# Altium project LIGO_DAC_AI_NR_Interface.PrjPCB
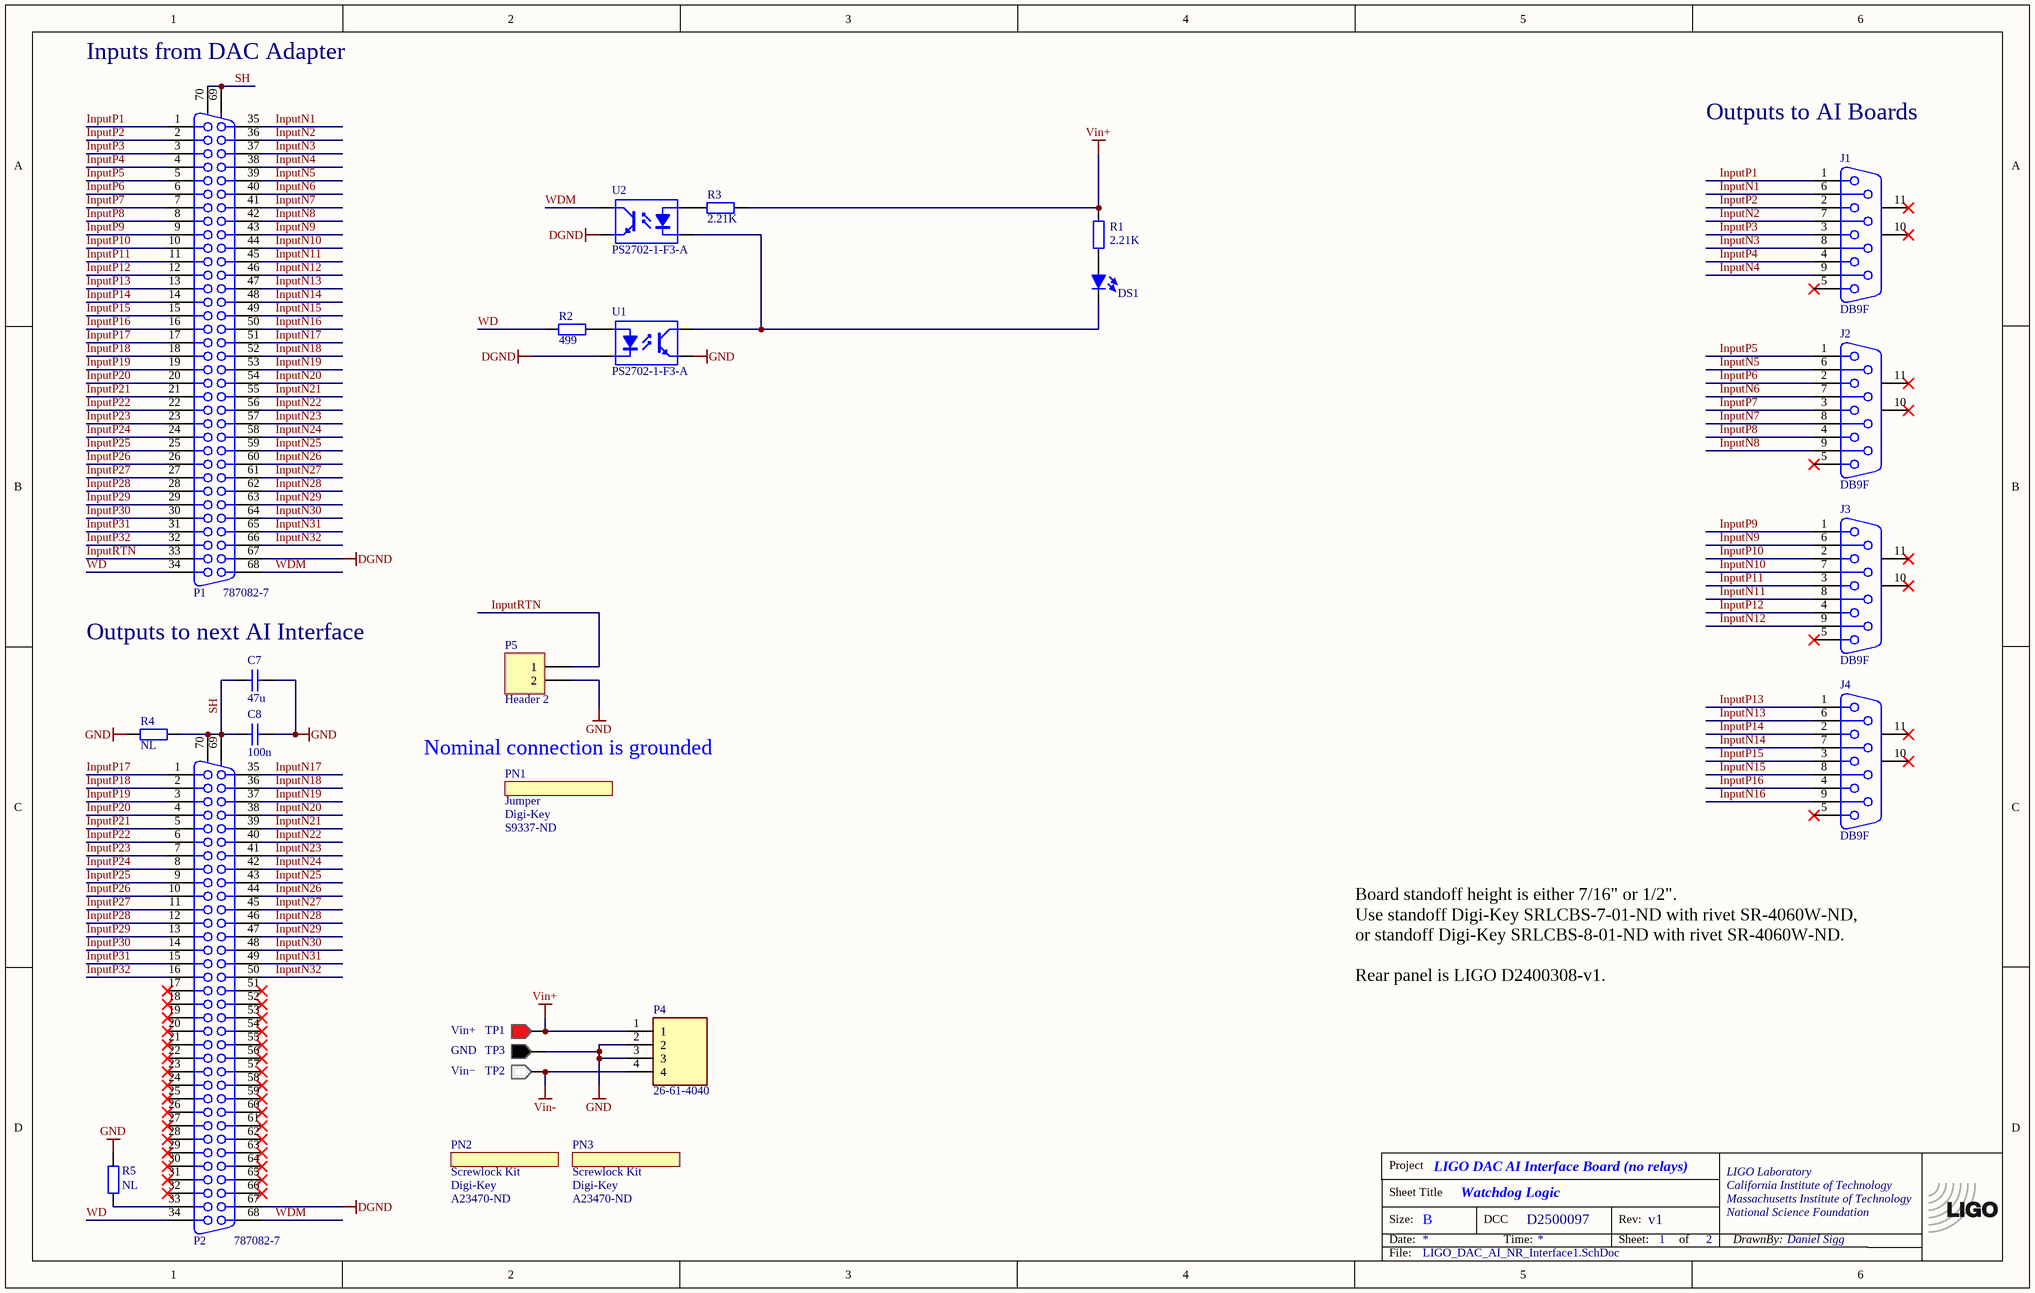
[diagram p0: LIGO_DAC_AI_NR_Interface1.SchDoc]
Rev: v1; Project: LIGO DAC AI Interface Board (no relays); Eng: Daniel Sigg; DCC: D2500097
1 sheet, 25 parts. Net scope: global (net labels, ports and power ports of the same name join across sheets).
Board file: LIGO_DAC_AI_NR_Interface.PcbDoc

## Sheet LIGO_DAC_AI_NR_Interface1.SchDoc: Watchdog Logic
size B; Engineer: Daniel Sigg; DocumentNumber: D2400023; Revision: v1; SheetNumber: 1; SheetTotal: 2; PageSetup: Record=PageOptions¦CenterHorizontal=True¦CenterVertical=True¦PrintScale=1.12¦XCorrection=1.00¦YCorrection=1.00¦PrintKind=0¦BorderSize=5000000¦LeftOffset=0¦BottomOffset=0¦Orientation=2¦PaperLength=1000¦PaperWidth=1000¦Scale=100¦PaperSource=15¦PrintQuality=600¦MediaType=1¦DitherType=10¦PaperKind=Tabloid¦PrintScaleMode=1; SHEETSIZE: B

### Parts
*?  TitleBlock  (value not drawn)  (graphical)
C7  47u  [CC5650-2220]
C8  100n  [CC2013-0805]
DS1  LED  [LED-1]  (value not drawn)
J1  DB9F  [DB9F-ST]
J2  DB9F  [DB9F-ST]
J3  DB9F  [DB9F-ST]
J4  DB9F  [DB9F-ST]
P1  787082-7  [787082-7]
P2  787082-7  [787082-7]
P4  26-61-4040  [HDRV4W155P0X396_1X4_1570X1001X1536P]
P5  Header 2  [TSW-102-XX-YY-S]
PN1  Jumper  Part Number: S9337-ND  Distributor: Digi-Key  (mechanical)
PN2  Screwlock Kit  Part Number: A23470-ND  Distributor: Digi-Key  (mechanical)
PN3  Screwlock Kit  Part Number: A23470-ND  Distributor: Digi-Key  (mechanical)
R1  2.21K  [CR2012-0805]
R2  499  [CR2012-0805]
R3  2.21K  [CR2012-0805]
R4  NL  [CR2012-0805]
R5  NL  [CR2012-0805]
TP1  Vin+  [TP1-RED]
TP2  Vin−  [TP1-WHT]
TP3  GND  [TP1-BLK]
U1  PS2702-1-F3-A  [PS2701A-1]
U2  PS2702-1-F3-A  [PS2701A-1]

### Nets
DGND: P1.67 P2.67 U1.2(K) U2.3(E)
GND: C7.1 C8.1 P4.2 P4.3 P5.2 R4.2 R5.2 TP3.1 U1.3(E)
Vin+: P4.1 R1.2 R3.2 TP1.1
Vin-: P4.4 TP2.1
InputN1: J1.6 P1.35
InputN2: J1.7 P1.36
InputN3: J1.8 P1.37
InputN4: J1.9 P1.38
InputN5: J2.6 P1.39
InputN6: J2.7 P1.40
InputN7: J2.8 P1.41
InputN8: J2.9 P1.42
InputN9: J3.6 P1.43
InputN10: J3.7 P1.44
InputN11: J3.8 P1.45
InputN12: J3.9 P1.46
InputN13: J4.6 P1.47
InputN14: J4.7 P1.48
InputN15: J4.8 P1.49
InputN16: J4.9 P1.50
InputN17: P1.51 P2.35
InputN18: P1.52 P2.36
InputN19: P1.53 P2.37
InputN20: P1.54 P2.38
InputN21: P1.55 P2.39
InputN22: P1.56 P2.40
InputN23: P1.57 P2.41
InputN24: P1.58 P2.42
InputN25: P1.59 P2.43
InputN26: P1.60 P2.44
InputN27: P1.61 P2.45
InputN28: P1.62 P2.46
InputN29: P1.63 P2.47
InputN30: P1.64 P2.48
InputN31: P1.65 P2.49
InputN32: P1.66 P2.50
InputP1: J1.1 P1.1
InputP2: J1.2 P1.2
InputP3: J1.3 P1.3
InputP4: J1.4 P1.4
InputP5: J2.1 P1.5
InputP6: J2.2 P1.6
InputP7: J2.3 P1.7
InputP8: J2.4 P1.8
InputP9: J3.1 P1.9
InputP10: J3.2 P1.10
InputP11: J3.3 P1.11
InputP12: J3.4 P1.12
InputP13: J4.1 P1.13
InputP14: J4.2 P1.14
InputP15: J4.3 P1.15
InputP16: J4.4 P1.16
InputP17: P1.17 P2.1
InputP18: P1.18 P2.2
InputP19: P1.19 P2.3
InputP20: P1.20 P2.4
InputP21: P1.21 P2.5
InputP22: P1.22 P2.6
InputP23: P1.23 P2.7
InputP24: P1.24 P2.8
InputP25: P1.25 P2.9
InputP26: P1.26 P2.10
InputP27: P1.27 P2.11
InputP28: P1.28 P2.12
InputP29: P1.29 P2.13
InputP30: P1.30 P2.14
InputP31: P1.31 P2.15
InputP32: P1.32 P2.16
InputRTN: P1.33 P5.1
SH: C7.2 C8.2 P1.69(MH1) P1.70(MH2) P2.69(MH1) P2.70(MH2) R4.1
WD: P1.34 P2.34 R2.1
WDM: P1.68 P2.68 U2.4(C)
NetDS1_1: DS1.1(K) U1.4(C) U2.2(K)
NetDS1_2: DS1.2(A) R1.1
NetP2_33: P2.33 R5.1
NetR2_2: R2.2 U1.1(A)
NetR3_1: R3.1 U2.1(A)

Not connected (* = marked no-connect by the designer): J1 5* 10(MH1)* 11(MH2)*; J2 5* 10(MH1)* 11(MH2)*; J3 5* 10(MH1)* 11(MH2)*; J4 5* 10(MH1)* 11(MH2)*; P2 17* 18* 19* 20* 21* 22* 23* 24* 25* 26* 27* 28* 29* 30* 31* 32* 51* 52* 53* 54* 55* 56* 57* 58* 59* 60* 61* 62* 63* 64* 65* 66*

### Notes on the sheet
- (near P1) Inputs from DAC Adapter
- Outputs to AI Boards
- Outputs to next AI Interface
- (near PN1) Nominal connection is grounded
- Board standoff height is either 7/16" or 1/2".
  Use standoff Digi-Key SRLCBS-7-01-ND with rivet SR-4060W-ND,
  or standoff Digi-Key SRLCBS-8-01-ND with rivet SR-4060W-ND.
  Rear panel is LIGO D2400308-v1.

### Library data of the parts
C7 = ChipCap: Capacitor, surface mount; Part Number: 445-C5750X7R1V476M230KCCT-ND; Tolerance: 10%; Voltage Rating: 35V
C8 = ChipCap: Capacitor, surface mount; Part Number: 311-1140-1-ND; Tolerance: 10%
DS1 = LED: Panel mount LED; Part Number: 67-1304-ND
J1-J4 = DB9F: Receptacle Assembly, 9 Position, Right Angle, .318 Series; Part Number: A34072-ND
P1 P2 = 787082-7: Receptacle Assembly, Shielded, Right Angle, AMPLIMITE; Part Number: A31814-ND
P4 = 26-61-4040: Connector; Manufacturer_Name: Molex; Part Number: WM5226-ND
P5 = Header 2: Header, 2-Pin; Part Number: SAM10844-ND
PN1 = Partlist
PN2 PN3 = Partlist: Jackscrew Socket, Slotted For AMPLIMITE Series: 786585-2
R1 R3 = ChipRes1: Resistor, surface mount; Part Number: 311-2.21KCRCT-ND; Tolerance: 1%
R2 = ChipRes1: Resistor, surface mount; Part Number: 311-499CRCT-ND; Tolerance: 1%
R4 R5 = ChipRes1: Resistor, surface mount; Tolerance: 1%
TP1 = TP_POSITIVE: Testpoint, red; Part Number: 5005K-ND
TP2 = TP_NEGATIVE: Testpoint, white; Part Number: 5007K-ND
TP3 = TP_GND: Testpoint, black; Part Number: 5006K-ND
U1 U2 = PS2701A: High Isolation Voltage SOP Photocoupler; Part Number: 559-1027-1-ND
